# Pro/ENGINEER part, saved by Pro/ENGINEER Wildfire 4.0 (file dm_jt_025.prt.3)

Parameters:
  METRIC = "NO"

Other parameters: PITCH, DRILL_POINT_ANGLE, DRILL_DEPTH, DRILL_DIAMETER, THREAD_DIAMETER, THREADS_PER_INCH, THREAD_DEPTH, THREAD_LENGTH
